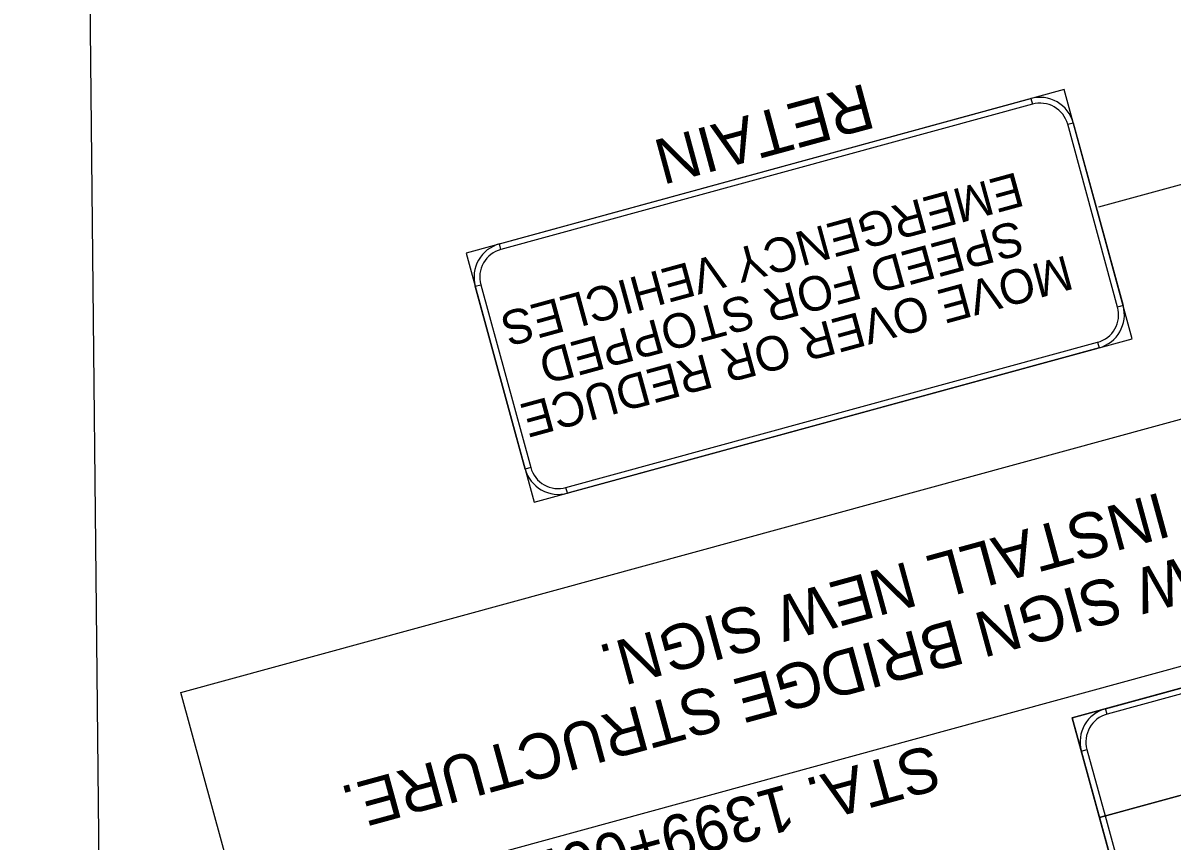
# Model space of a CAD drawing. Extents: x 2001876 to 2025694, y 804561 to 868938.
# Drawn here: x 2010635 to 2011142, y 826193 to 826554 of the extents above; entities that cross this region are included whole.
import ezdxf

# ---------------------------------------------------------------- set-up
doc = ezdxf.new("R2010")
doc.units = 0
for name, color, linetype in [('RD_SHT_ShtClip', 7, 'Continuous'), ('TR SN EXTRUDED PANEL SIGNS - GROUND MOUNTED', 7, 'Continuous'), ('TR SN EXTRUDED PANEL SIGNS- MOUNTED OVERHEAD', 7, 'Continuous')]:
    doc.layers.add(name, color=color, linetype=linetype)

msp = doc.modelspace()

# ---------------------------------------------------------------- linework, layer by layer
at = {"layer": 'RD_SHT_ShtClip'}
msp.add_line((2010698.28, 823374.8), (2010635.06, 829374.39), dxfattribs=at)
at = {"layer": 'TR SN EXTRUDED PANEL SIGNS - GROUND MOUNTED'}
for p, q in [((2011109.9, 826472.4), (2011356.3, 826539.76)), ((2011079.9, 826520.16), (2011080.57, 826517.71)), ((2011096.13, 826508.83), (2011098.57, 826509.5)), ((2010845.97, 826453.58), (2010845.31, 826456.03)), ((2010834.65, 826437.36), (2010837.1, 826438.03)), ((2011120.61, 826428.86), (2011118.17, 826428.19)), ((2011109.29, 826412.63), (2011109.96, 826410.19)), ((2010859.14, 826357.38), (2010856.7, 826356.72)), ((2010875.37, 826346.06), (2010874.7, 826348.51))]:
    msp.add_line(p, q, dxfattribs=at)
for points in [[(2011094.56, 826524.16), (2010830.64, 826452.02), (2010860.7, 826342.05), (2011124.62, 826414.2), (2011094.56, 826524.16)], [(2011080.57, 826517.71), (2010845.97, 826453.58), (2010845.31, 826456.03), (2011079.9, 826520.16), (2011080.57, 826517.71)], [(2011118.17, 826428.19), (2011096.13, 826508.83), (2011098.57, 826509.5), (2011120.61, 826428.86), (2011118.17, 826428.19)], [(2010837.1, 826438.03), (2010859.14, 826357.38), (2010856.7, 826356.72), (2010834.65, 826437.36), (2010837.1, 826438.03)], [(2010874.7, 826348.51), (2011109.29, 826412.63), (2011109.96, 826410.19), (2010875.37, 826346.06), (2010874.7, 826348.51)]]:
    msp.add_lwpolyline(points, close=True, dxfattribs=at)
for centre, radius, start, end in [((2011083.91, 826505.49), 15.2, 15.2886, 105.2889), ((2011083.91, 826505.49), 12.67, 15.2886, 105.2889), ((2010849.31, 826441.37), 15.2, 105.2889, 195.2891), ((2010849.31, 826441.37), 12.67, 105.2889, 195.2891), ((2011105.95, 826424.85), 12.67, 285.289, 15.2886), ((2011105.95, 826424.85), 15.2, 285.289, 15.2886), ((2010871.36, 826360.72), 15.2, 195.2888, 285.289), ((2010871.36, 826360.72), 12.67, 195.2888, 285.289)]:
    msp.add_arc(centre, radius, start, end, dxfattribs=at)
at = {"layer": 'TR SN EXTRUDED PANEL SIGNS- MOUNTED OVERHEAD'}
for p, q in [((2011113.49, 826248.53), (2011112.82, 826250.98)), ((2011102.16, 826232.31), (2011104.61, 826232.97))]:
    msp.add_line(p, q, dxfattribs=at)
for points in [[(2011327.14, 826319.09), (2010732.52, 826156.54), (2010704.76, 826258.09), (2011299.38, 826420.64)], [(2011406.06, 826331.14), (2011098.16, 826246.97), (2011110.18, 826202.98), (2011418.08, 826287.15), (2011406.06, 826331.14)], [(2011418.08, 826287.15), (2011110.18, 826202.98), (2011098.16, 826246.97), (2011406.06, 826331.14)], [(2011462.17, 826125.87), (2011154.27, 826041.7), (2011098.16, 826246.97), (2011406.06, 826331.14)], [(2011392.06, 826324.68), (2011113.49, 826248.53), (2011112.82, 826250.98), (2011391.4, 826327.13), (2011392.06, 826324.68)], [(2011418.08, 826287.15), (2011110.18, 826202.98), (2011154.27, 826041.7), (2011462.17, 826125.87), (2011418.08, 826287.15)], [(2011104.61, 826232.97), (2011112.62, 826203.65), (2011110.18, 826202.98), (2011102.16, 826232.31), (2011104.61, 826232.97)], [(2011112.62, 826203.65), (2011152.7, 826057.03), (2011150.26, 826056.36), (2011110.18, 826202.98), (2011112.62, 826203.65)]]:
    msp.add_lwpolyline(points, close=True, dxfattribs=at)
for radius in [15.2, 12.67]:
    msp.add_arc((2011116.83, 826236.31), radius, 105.2889, 195.2891, dxfattribs=at)

# ---------------------------------------------------------------- texts
at = {"layer": 'TR SN EXTRUDED PANEL SIGNS - GROUND MOUNTED'}
for s, p in [('EMERGENCY VEHICLES', (2011073.79, 826487.83)), ('SPEED FOR STOPPED', (2011074.1, 826466.6)), ('MOVE OVER OR REDUCE', (2011095.58, 826451.15))]:
    msp.add_text(s, height=15.2, rotation=195.2888, dxfattribs=at).set_placement(p)
at = {"layer": 'TR SN EXTRUDED PANEL SIGNS- MOUNTED OVERHEAD'}
for s, rotation, p in [('RETAIN', 195.1773, (2011006.9, 826527)), ('ERECT NEW SIGN BRIDGE STRUCTURE.', 195.2888, (2011278.66, 826354.15)), ('INSTALL NEW SIGN.', 195.2888, (2011137.45, 826346.65)), ('STA. 1399+00.00', 195.2888, (2011036.53, 826235.37))]:
    msp.add_text(s, height=20, rotation=rotation, dxfattribs=at).set_placement(p)

doc.saveas('drawing.dxf')
